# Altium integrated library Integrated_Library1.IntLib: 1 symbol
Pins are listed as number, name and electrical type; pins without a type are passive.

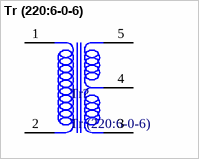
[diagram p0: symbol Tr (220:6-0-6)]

## Tr (220:6-0-6)
designator Tr?
footprint Tr (220:6-0-6)
footprint Tr (220:6-0-6)
pins: 1 Ph, 2 N, 3 6, 4 0, 5 6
